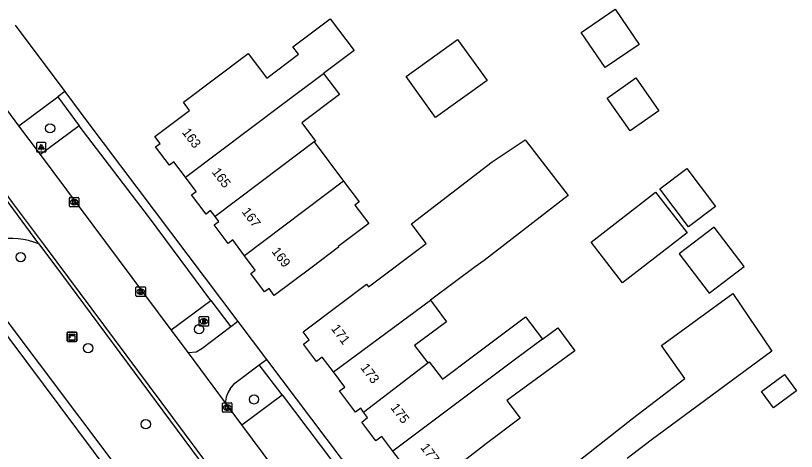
# Model space of a CAD drawing. Extents: x 164494 to 166241, y 382475 to 384494.
# Drawn here: x 165007.7 to 165090.4, y 383195 to 383241.1 of the extents above; entities that cross this region are included whole.
import ezdxf

# ---------------------------------------------------------------- set-up
doc = ezdxf.new("R2010")
doc.units = 0
for name, color, linetype in [('IMGEO_Berm_halfverhard', 7, 'Continuous'), ('IMGEO_Boom', 7, 'Continuous'), ('IMGEO_Haag', 7, 'Continuous'), ('IMGEO_Hek', 7, 'Continuous'), ('IMGEO_Kast', 7, 'Continuous'), ('IMGEO_Kolk', 7, 'Continuous'), ('IMGEO_Lichtpunt', 7, 'Continuous'), ('IMGEO_Pand', 7, 'Continuous'), ('IMGEO_Pand_nummerreeks', 7, 'Continuous'), ('IMGEO_Parkeervlak_open', 7, 'Continuous'), ('IMGEO_Rijbaan_lokaal_gesloten', 7, 'Continuous'), ('IMGEO_Rioolput', 7, 'Continuous'), ('IMGEO_Voetpad_halfverhard', 7, 'Continuous'), ('IMGEO_Voetpad_open', 7, 'Continuous')]:
    doc.layers.add(name, color=color, linetype=linetype)

msp = doc.modelspace()

# ---------------------------------------------------------------- linework, layer by layer
at = {"layer": 'IMGEO_Berm_halfverhard'}
msp.add_lwpolyline([(165010.162, 383216.934), (165012.663, 383213.574), (165041.519, 383174.67), (165059.934, 383149.875), (165074.189, 383130.821), (165074.54, 383131.069)], dxfattribs=at)
at = {"layer": 'IMGEO_Boom'}
for centre in [(165011.341, 383229.17), (165008.231, 383215.532), (165027.124, 383207.892), (165015.366, 383205.887), (165032.942, 383200.456), (165021.479, 383197.829)]:
    msp.add_circle(centre, 0.489, dxfattribs=at)
at = {"layer": 'IMGEO_Haag'}
for points in [[(165057.111, 383141.834), (165001.652, 383215.597)], [(164990.882, 383140.55), (164991.336, 383140.194), (164999.033, 383132.273), (165005.383, 383122.26), (165055.217, 383142.364), (165001.686, 383214.058), (164971.559, 383197.218), (164924.278, 383170.366), (164950.628, 383163.159), (164961.434, 383158.935), (164968.553, 383155.492), (164979.763, 383149.202)]]:
    msp.add_lwpolyline(points, dxfattribs=at)
at = {"layer": 'IMGEO_Hek'}
msp.add_lwpolyline([(165005.383, 383122.26), (165055.217, 383142.364), (165001.686, 383214.058), (164971.559, 383197.218), (164924.278, 383170.366), (164950.628, 383163.159), (164961.434, 383158.935), (164968.553, 383155.492), (164979.763, 383149.202)], dxfattribs=at)
at = {"layer": 'IMGEO_Kast'}
for p, q in [((165013.162, 383206.67), (165013.162, 383207.511)), ((165013.162, 383207.511), (165013.162, 383206.67)), ((165013.237, 383207.595), (165014.078, 383207.595)), ((165014.078, 383207.595), (165013.237, 383207.595)), ((165014.162, 383207.52), (165014.162, 383206.679)), ((165014.162, 383206.679), (165014.162, 383207.52)), ((165014.087, 383206.595), (165013.246, 383206.595)), ((165013.246, 383206.595), (165014.087, 383206.595))]:
    msp.add_line(p, q, dxfattribs=at)
for points in [[(165013.357, 383207.385), (165013.957, 383207.385), (165013.957, 383207.3), (165013.357, 383207.3), (165013.357, 383207.385)], [(165013.357, 383207.21), (165013.957, 383207.21), (165013.957, 383206.721), (165013.357, 383206.721), (165013.357, 383207.21)]]:
    msp.add_lwpolyline(points, dxfattribs=at)
msp.add_circle((165013.441, 383207.059), 0.0377, dxfattribs=at)
for centre, start, end in [((165013.24, 383207.517), 92.4484, 184.28452), ((165013.24, 383207.517), 92.4484, 184.28452), ((165014.084, 383207.517), 2.4484, 94.28452), ((165014.084, 383207.517), 2.4484, 94.28452), ((165013.24, 383206.673), 182.4484, 274.28452), ((165013.24, 383206.673), 182.4484, 274.28452), ((165014.084, 383206.673), 272.4484, 4.28452), ((165014.084, 383206.673), 272.4484, 4.28452)]:
    msp.add_arc(centre, 0.0779, start, end, dxfattribs=at)
at = {"layer": 'IMGEO_Kolk'}
for p, q in [((165013.384, 383220.933), (165013.384, 383221.785)), ((165013.459, 383221.859), (165014.311, 383221.859)), ((165013.872, 383221.639), (165013.897, 383221.639)), ((165014.385, 383221.785), (165014.385, 383220.933)), ((165014.311, 383220.859), (165013.459, 383220.859)), ((165013.895, 383221.079), (165013.87, 383221.079)), ((165020.44, 383211.447), (165020.44, 383212.299)), ((165020.515, 383212.373), (165021.367, 383212.373)), ((165021.441, 383212.299), (165021.441, 383211.447)), ((165021.367, 383211.373), (165020.515, 383211.373)), ((165020.951, 383211.593), (165020.926, 383211.593)), ((165020.928, 383212.153), (165020.953, 383212.153)), ((165029.61, 383199.166), (165029.61, 383200.018)), ((165029.685, 383200.092), (165030.537, 383200.092)), ((165030.098, 383199.872), (165030.123, 383199.872)), ((165030.611, 383200.018), (165030.611, 383199.166)), ((165030.537, 383199.092), (165029.685, 383199.092)), ((165030.121, 383199.312), (165030.096, 383199.312))]:
    msp.add_line(p, q, dxfattribs=at)
for points in [[(165013.384, 383220.933), (165013.384, 383221.785)], [(165013.459, 383221.859), (165014.311, 383221.859)], [(165013.705, 383221.559), (165013.828, 383221.559), (165013.828, 383221.408), (165013.958, 383221.559), (165014.122, 383221.559), (165013.976, 383221.408), (165014.129, 383221.159), (165013.977, 383221.159), (165013.892, 383221.323), (165013.828, 383221.256), (165013.828, 383221.159), (165013.705, 383221.159), (165013.705, 383221.559)], [(165014.385, 383221.785), (165014.385, 383220.933)], [(165014.311, 383220.859), (165013.459, 383220.859)], [(165020.44, 383211.447), (165020.44, 383212.299)], [(165020.515, 383212.373), (165021.367, 383212.373)], [(165021.441, 383212.299), (165021.441, 383211.447)], [(165021.367, 383211.373), (165020.515, 383211.373)], [(165020.761, 383212.073), (165020.884, 383212.073), (165020.884, 383211.922), (165021.014, 383212.073), (165021.178, 383212.073), (165021.032, 383211.922), (165021.185, 383211.673), (165021.033, 383211.673), (165020.948, 383211.837), (165020.884, 383211.77), (165020.884, 383211.673), (165020.761, 383211.673), (165020.761, 383212.073)], [(165029.61, 383199.166), (165029.61, 383200.018)], [(165029.685, 383200.092), (165030.537, 383200.092)], [(165029.931, 383199.792), (165030.054, 383199.792), (165030.054, 383199.641), (165030.184, 383199.792), (165030.348, 383199.792), (165030.202, 383199.641), (165030.355, 383199.392), (165030.203, 383199.392), (165030.118, 383199.556), (165030.054, 383199.489), (165030.054, 383199.392), (165029.931, 383199.392), (165029.931, 383199.792)], [(165030.611, 383200.018), (165030.611, 383199.166)], [(165030.537, 383199.092), (165029.685, 383199.092)]]:
    msp.add_lwpolyline(points, dxfattribs=at)
for centre, start, end in [((165013.461, 383221.783), 91.55205, 178.44795), ((165013.461, 383221.783), 91.55205, 178.44795), ((165014.309, 383221.783), 1.55205, 88.44795), ((165014.309, 383221.783), 1.55205, 88.44795), ((165013.461, 383220.935), 181.55205, 268.44795), ((165013.461, 383220.935), 181.55205, 268.44795), ((165014.309, 383220.935), 271.55205, 358.44795), ((165014.309, 383220.935), 271.55205, 358.44795), ((165020.517, 383212.297), 91.55205, 178.44795), ((165020.517, 383212.297), 91.55205, 178.44795), ((165021.365, 383212.297), 1.55205, 88.44795), ((165021.365, 383212.297), 1.55205, 88.44795), ((165020.517, 383211.449), 181.55205, 268.44795), ((165020.517, 383211.449), 181.55205, 268.44795), ((165021.365, 383211.449), 271.55205, 358.44795), ((165021.365, 383211.449), 271.55205, 358.44795), ((165029.687, 383200.016), 91.55205, 178.44795), ((165029.687, 383200.016), 91.55205, 178.44795), ((165030.535, 383200.016), 1.55205, 88.44795), ((165030.535, 383200.016), 1.55205, 88.44795), ((165029.687, 383199.168), 181.55205, 268.44795), ((165029.687, 383199.168), 181.55205, 268.44795), ((165030.535, 383199.168), 271.55205, 358.44795), ((165030.535, 383199.168), 271.55205, 358.44795)]:
    msp.add_arc(centre, 0.0765, start, end, dxfattribs=at)
for centre, major_axis, ratio, start_param, end_param in [((165013.871, 383221.359), (-0.387, 0.002), 0.722429, 4.712389, 7.853982), ((165013.896, 383221.359), (-0.39, 0.002), 0.717154, 1.570796, 4.712389), ((165020.927, 383211.873), (-0.387, 0.002), 0.722429, 4.712389, 7.853982), ((165020.952, 383211.873), (-0.39, 0.002), 0.717154, 1.570796, 4.712389), ((165030.097, 383199.592), (-0.387, 0.002), 0.722429, 4.712389, 7.853982), ((165030.122, 383199.592), (-0.39, 0.002), 0.717154, 1.570796, 4.712389)]:
    msp.add_ellipse(centre, major_axis=major_axis, ratio=ratio, start_param=start_param, end_param=end_param, dxfattribs=at)
at = {"layer": 'IMGEO_Lichtpunt'}
for p, q in [((165009.912, 383227.57), (165009.912, 383226.763)), ((165009.912, 383227.57), (165009.912, 383226.763)), ((165010.814, 383227.665), (165010.006, 383227.665)), ((165010.814, 383227.665), (165010.006, 383227.665)), ((165010.908, 383226.763), (165010.908, 383227.57)), ((165010.908, 383226.763), (165010.908, 383227.57)), ((165010.006, 383226.669), (165010.814, 383226.669)), ((165010.006, 383226.669), (165010.814, 383226.669))]:
    msp.add_line(p, q, dxfattribs=at)
for points in [[(165010.286, 383227.234), (165010.325, 383227.206), (165010.137, 383226.944), (165010.099, 383226.971), (165010.286, 383227.234)], [(165010.388, 383227.186), (165010.435, 383227.186), (165010.435, 383226.864), (165010.388, 383226.864), (165010.388, 383227.186)], [(165010.498, 383227.206), (165010.536, 383227.233), (165010.723, 383226.971), (165010.684, 383226.943), (165010.498, 383227.206)]]:
    msp.add_lwpolyline(points, dxfattribs=at)
msp.add_circle((165010.411, 383227.368), 0.0994, dxfattribs=at)
for centre, start, end in [((165010.006, 383227.57), 90, 180), ((165010.006, 383227.57), 90, 180), ((165010.814, 383227.57), 0, 90), ((165010.814, 383227.57), 0, 90), ((165010.006, 383226.763), 180, 270), ((165010.006, 383226.763), 180, 270), ((165010.814, 383226.763), 270, 0), ((165010.814, 383226.763), 270, 360)]:
    msp.add_arc(centre, 0.0946, start, end, dxfattribs=at)
at = {"layer": 'IMGEO_Pand'}
for points in [[(165067.596, 383239.343), (165071.211, 383241.801), (165073.756, 383238.059), (165070.141, 383235.601), (165067.596, 383239.343)], [(165025.693, 383223.987), (165024.46, 383225.628), (165023.981, 383225.268), (165022.515, 383227.218), (165022.994, 383227.578), (165022.444, 383228.31), (165026.116, 383231.071), (165025.463, 383231.939), (165032.34, 383237.107), (165034.309, 383234.487), (165037.665, 383237.013), (165037.064, 383237.812), (165041.018, 383240.789), (165043.542, 383237.432), (165040.306, 383234.996)], [(165052.184, 383230.308), (165049.053, 383234.664), (165054.509, 383238.585), (165057.64, 383234.23), (165052.184, 383230.308)], [(165025.693, 383223.987), (165036.095, 383231.826), (165040.306, 383234.996)], [(165040.306, 383234.996), (165041.999, 383232.745), (165037.992, 383229.754), (165039.442, 383227.824), (165039.32, 383227.733)], [(165070.347, 383232.379), (165073.395, 383234.508), (165075.828, 383231.026), (165072.78, 383228.896), (165070.347, 383232.379)], [(165041.352, 383203.364), (165040.174, 383204.932), (165039.56, 383204.471), (165038.171, 383206.319), (165038.784, 383206.78), (165038.158, 383207.613), (165042.156, 383210.617), (165044.86, 383212.649), (165045.063, 383212.378), (165051.186, 383216.981), (165049.617, 383219.07), (165058.178, 383225.614), (165061.671, 383227.945), (165066.223, 383222.066), (165057.315, 383215.185), (165056.376, 383214.489), (165054.302, 383212.954), (165051.631, 383210.976)], [(165039.32, 383227.733), (165035.845, 383225.12), (165028.815, 383219.834)], [(165039.32, 383227.733), (165042.434, 383223.59)], [(165075.941, 383222.766), (165078.81, 383224.929), (165081.844, 383220.903), (165078.974, 383218.74), (165075.941, 383222.766)], [(165028.815, 383219.834), (165028.345, 383220.458), (165027.866, 383220.098), (165026.332, 383222.139), (165026.812, 383222.499), (165025.693, 383223.987)], [(165042.434, 383223.59), (165044.092, 383221.384), (165043.63, 383221.036), (165045.093, 383219.09), (165041.852, 383216.653), (165041.899, 383216.591), (165039.091, 383214.48), (165035.095, 383211.477), (165034.545, 383212.208), (165034.065, 383211.847), (165032.597, 383213.802), (165033.077, 383214.162), (165031.936, 383215.681)], [(165042.434, 383223.59), (165031.936, 383215.681)], [(165075.49, 383222.399), (165078.818, 383218.091), (165071.972, 383212.803), (165068.644, 383217.111), (165075.49, 383222.399)], [(165031.936, 383215.681), (165030.685, 383217.345), (165030.205, 383216.984), (165028.74, 383218.935), (165029.22, 383219.295), (165028.815, 383219.834)], [(165081.684, 383218.687), (165077.998, 383215.877), (165081.164, 383211.724), (165084.85, 383214.533), (165081.684, 383218.687)], [(165057.061, 383182.578), (165055.907, 383184.106), (165055.28, 383183.633), (165053.752, 383185.657), (165054.378, 383186.13), (165053.869, 383186.804), (165057.867, 383189.808), (165060.586, 383191.852), (165062.046, 383189.909), (165065.549, 383192.541), (165073.025, 383198.419), (165078.583, 383202.656), (165076.095, 383206.151), (165083.664, 383211.659), (165087.792, 383205.569), (165075.031, 383196.131), (165072.484, 383194.21)], [(165041.352, 383203.364), (165051.631, 383210.976)], [(165051.631, 383210.976), (165053.321, 383208.692), (165049.929, 383206.18), (165051.355, 383204.324)], [(165051.355, 383204.324), (165051.511, 383204.444), (165052.899, 383202.597), (165056.183, 383205.065), (165061.704, 383209.216), (165063.52, 383206.844)], [(165063.52, 383206.844), (165065.122, 383208.035), (165066.933, 383205.599), (165059.726, 383200.352), (165061.149, 383198.459), (165057.586, 383195.781), (165054.871, 383193.698), (165050.874, 383190.694), (165050.291, 383191.47), (165049.732, 383191.049), (165048.25, 383193.021), (165048.81, 383193.441), (165047.656, 383194.976)], [(165063.52, 383206.844), (165060.641, 383204.704), (165047.656, 383194.976)], [(165044.554, 383199.103), (165051.355, 383204.324)], [(165044.554, 383199.103), (165044.243, 383199.517), (165043.706, 383199.114), (165042.014, 383201.366), (165042.551, 383201.769), (165041.352, 383203.364)], [(165089.13, 383203.08), (165090.398, 383201.366), (165087.971, 383199.571), (165086.703, 383201.285), (165089.13, 383203.08)], [(165047.656, 383194.976), (165046.486, 383196.532), (165045.857, 383196.059), (165044.352, 383198.061), (165044.982, 383198.534), (165044.554, 383199.103)]]:
    msp.add_lwpolyline(points, dxfattribs=at)
at = {"layer": 'IMGEO_Parkeervlak_open'}
for points in [[(165007.637, 383240.088), (165012.902, 383233.067)], [(165008.04, 383229.432), (165012.159, 383232.511)], [(165014.428, 383229.447), (165010.316, 383226.399)], [(165024.153, 383207.813), (165028.355, 383210.944)], [(165031.646, 383197.767), (165035.91, 383200.939)]]:
    msp.add_lwpolyline(points, dxfattribs=at)
at = {"layer": 'IMGEO_Rijbaan_lokaal_gesloten'}
for points in [[(164958.624, 383286.837), (164967.779, 383274.687), (165004.939, 383224.601), (165007.308, 383221.332), (165010.834, 383216.638), (165074.54, 383131.069)], [(165008.04, 383229.432), (165002.791, 383236.502)], [(165010.316, 383226.399), (165008.04, 383229.432)], [(165024.153, 383207.813), (165010.316, 383226.399)], [(165025.987, 383205.384), (165024.153, 383207.813)], [(165029.916, 383200.087), (165025.987, 383205.384)], [(165031.646, 383197.767), (165029.916, 383200.087)], [(165039.657, 383187.007), (165031.646, 383197.767)]]:
    msp.add_lwpolyline(points, dxfattribs=at)
at = {"layer": 'IMGEO_Rioolput'}
for p, q in [((165027.134, 383208.301), (165027.134, 383209.153)), ((165027.209, 383209.227), (165028.061, 383209.227)), ((165027.622, 383209.007), (165027.647, 383209.007)), ((165028.135, 383209.153), (165028.135, 383208.301)), ((165028.061, 383208.227), (165027.209, 383208.227)), ((165027.645, 383208.447), (165027.62, 383208.447))]:
    msp.add_line(p, q, dxfattribs=at)
for points in [[(165027.134, 383208.301), (165027.134, 383209.153)], [(165027.209, 383209.227), (165028.061, 383209.227)], [(165027.723, 383208.925), (165027.471, 383208.927), (165027.471, 383208.527)], [(165028.135, 383209.153), (165028.135, 383208.301)], [(165028.061, 383208.227), (165027.209, 383208.227)], [(165027.471, 383208.527), (165027.595, 383208.527), (165027.595, 383208.689), (165027.606, 383208.689)], [(165027.649, 383208.846), (165027.595, 383208.846), (165027.595, 383208.765)], [(165027.595, 383208.765), (165027.647, 383208.765)], [(165027.653, 383208.66), (165027.724, 383208.527), (165027.864, 383208.527), (165027.799, 383208.653)]]:
    msp.add_lwpolyline(points, dxfattribs=at)
for centre, radius, start, end in [((165027.211, 383209.151), 0.0765, 91.55205, 178.44795), ((165027.211, 383209.151), 0.0765, 91.55205, 178.44795), ((165027.722, 383208.815), 0.109, 350.36119, 89.41601), ((165028.059, 383209.151), 0.0765, 1.55205, 88.44795), ((165028.059, 383209.151), 0.0765, 1.55205, 88.44795), ((165027.211, 383208.303), 0.0765, 181.55205, 268.44795), ((165027.211, 383208.303), 0.0765, 181.55205, 268.44795), ((165027.605, 383208.636), 0.0533, 26.02933, 88.69889), ((165027.631, 383208.954), 0.19, 274.7715, 282.96867), ((165027.655, 383208.75), 0.0964, 77.00612, 93.18647), ((165027.669, 383208.807), 0.0378, 276.66336, 79.67722), ((165027.72, 383208.815), 0.112, 277.58423, 350.98172), ((165027.704, 383208.6), 0.108, 29.51342, 73.79051), ((165028.059, 383208.303), 0.0765, 271.55205, 358.44795), ((165028.059, 383208.303), 0.0765, 271.55205, 358.44795)]:
    msp.add_arc(centre, radius, start, end, dxfattribs=at)
for centre, major_axis, ratio, start_param, end_param in [((165027.621, 383208.727), (-0.387, 0.002), 0.722429, 4.712389, 7.853982), ((165027.646, 383208.727), (-0.39, 0.002), 0.717154, 1.570796, 4.712389)]:
    msp.add_ellipse(centre, major_axis=major_axis, ratio=ratio, start_param=start_param, end_param=end_param, dxfattribs=at)
at = {"layer": 'IMGEO_Voetpad_halfverhard'}
msp.add_lwpolyline([(165010.162, 383216.934), (165004.699, 383224.274)], dxfattribs=at)
msp.add_arc((165007.051, 383208.981), 8.54, 68.63845, 129.21898, dxfattribs=at)
at = {"layer": 'IMGEO_Voetpad_open'}
for points in [[(165012.902, 383233.067), (165012.159, 383232.511)], [(165012.902, 383233.067), (165015.239, 383229.95), (165031.244, 383208.7)], [(165012.159, 383232.511), (165014.428, 383229.447)], [(165028.355, 383210.944), (165021.887, 383219.675), (165014.428, 383229.447)], [(165028.355, 383210.944), (165030.492, 383208.133)], [(165030.492, 383208.133), (165027.415, 383205.813), (165026.806, 383205.467), (165025.987, 383205.384)], [(165031.244, 383208.7), (165030.492, 383208.133)], [(165031.244, 383208.7), (165034.273, 383204.678)], [(165030.4, 383201.58), (165030.905, 383202.188), (165033.499, 383204.106)], [(165033.499, 383204.106), (165034.273, 383204.678)], [(165035.91, 383200.939), (165033.499, 383204.106)], [(165034.273, 383204.678), (165046.93, 383187.872)], [(165035.91, 383200.939), (165043.994, 383190.272)]]:
    msp.add_lwpolyline(points, dxfattribs=at)
msp.add_arc((165032.787, 383199.981), 2.873, 146.18542, 177.89132, dxfattribs=at)

# ---------------------------------------------------------------- texts
at = {"layer": 'IMGEO_Pand_nummerreeks'}
for s, p in [('163', (165025.266, 383228.748)), ('165', (165028.428, 383224.54)), ('167', (165031.591, 383220.332)), ('169', (165034.754, 383216.123)), ('171', (165041.057, 383207.949)), ('173', (165044.167, 383203.811)), ('175', (165047.346, 383199.581)), ('177', (165050.525, 383195.351))]:
    msp.add_text(s, height=1, rotation=306.92692, dxfattribs=at).set_placement(p)

doc.saveas('drawing.dxf')
